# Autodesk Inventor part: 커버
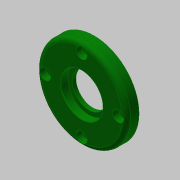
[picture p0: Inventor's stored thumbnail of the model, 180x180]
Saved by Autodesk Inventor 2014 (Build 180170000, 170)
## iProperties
Created: 2019-09
Part Number: 커버
Material: 알루미늄 6061
Document SubType Name: Modeling
Designer: mduedu
Density: 1 g/cm^3
Appearance: Dark Green
Author: mduedu
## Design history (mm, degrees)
sketch "스케치1"
  geometry: C1 r 32 at (0, 0); 1 further point
  constraints: 1 centre point, 1 coincident
  dimensions: "d0" = 64 diameter of C1
extrude "돌출1" new body sketch "스케치1" distance "d1" = 9; taper "d2" = 0 deg
sketch "스케치2"
  geometry: C1 r 21 at (0, 0); 1 further point
  constraints: 1 centre point, 1 coincident
  dimensions: "d3" = 42 diameter of C1
extrude "돌출2" join sketch "스케치2" distance "d4" = 3; taper "d5" = 0 deg
hole "구멍1" diameter "d8" = 24; stored, may be unused: countersink angle "d12" = 90 deg, drill point angle "d14" = 118 deg; dims "d6" = 10, "d7" = 10, "d9" = 6, "d10" = 30, "d11" = 5.2, "d13" = 8
hole "구멍2" diameter "d17" = 37; stored, may be unused: countersink angle "d21" = 90 deg, drill point angle "d23" = 0 deg; dims "d15" = 10, "d16" = 10, "d18" = 6, "d19" = 30, "d20" = 5.2, "d22" = 4
fillet "모깎기1" dims "d24" = 3
fillet "모깎기2" dims "d25" = 3
chamfer "모따기1" distance "d27" = 0.5; stored, may be unused: second distance "d28" = 2, angle "d29" = 30 deg
chamfer "모따기2" distance "d30" = 1; stored, may be unused: second distance "d31" = 2, angle "d32" = 30 deg
sketch "스케치3" dims "d33" = 52
  geometry: 3 further points
  constraints: 2 vertical alignment, 1 coincident, 2 other
hole "구멍3" sketch "스케치3" at (0, 26) diameter "d34" = 4.5; stored, may be unused: countersink angle "d38" = 90 deg, drill point angle "d40" = 0 deg; dims "d35" = 6, "d36" = 8, "d37" = 4.4, "d39" = 4
node "솔리드1"
pattern_circular "원형 패턴1" dims angle "d42" = 360 deg
